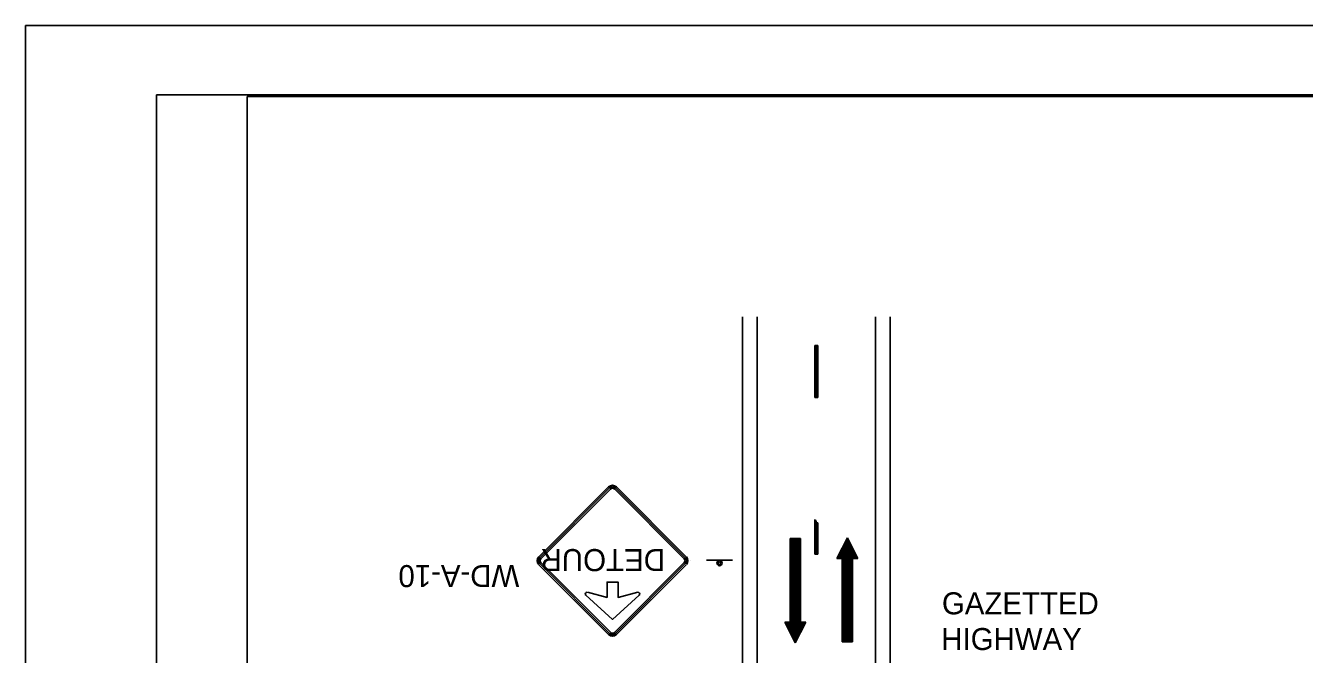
# Model space of a CAD drawing. Extents: x 1482 to 1692, y 225 to 494.
# Drawn here: x 1482.4 to 1587.1, y 442.2 to 493.6 of the extents above; entities that cross this region are included whole.
import ezdxf

# ---------------------------------------------------------------- set-up
doc = ezdxf.new("R2010")
doc.units = 0
for name, color, linetype in [('Level 1', 7, 'Continuous'), ('Level 17', 7, 'Continuous'), ('Level 2', 7, 'Continuous'), ('Level 60', 7, 'Continuous')]:
    doc.layers.add(name, color=color, linetype=linetype)

msp = doc.modelspace()

# ---------------------------------------------------------------- linework, layer by layer
at = {"layer": 'Level 1'}
msp.add_line((1493.13, 487.96), (1493.13, 487.96), dxfattribs=at)
at = {"layer": 'Level 17'}
for p, q in [((1524.41, 450.17), (1530.12, 455.89)), ((1524.49, 450.08), (1530.21, 455.8)), ((1524.58, 450), (1530.3, 455.72)), ((1530.6, 455.72), (1536.32, 450)), ((1530.69, 455.8), (1536.4, 450.08)), ((1530.77, 455.89), (1536.49, 450.17)), ((1530.12, 443.8), (1524.41, 449.52)), ((1530.21, 443.89), (1524.49, 449.61)), ((1530.3, 443.97), (1524.58, 449.69)), ((1536.32, 449.69), (1530.6, 443.97)), ((1536.4, 449.61), (1530.69, 443.89)), ((1536.49, 449.52), (1530.77, 443.8)), ((1536.81, 449.85), (1536.81, 449.85)), ((1540.28, 449.88), (1538.14, 449.88)), ((1532.51, 447.26), (1532.51, 447.26)), ((1532.51, 447.26), (1532.51, 447.26)), ((1532.51, 447.26), (1532.51, 447.26))]:
    msp.add_line(p, q, dxfattribs=at)
for points in [[(1528.39, 447.26), (1530, 446.84), (1530, 448.1), (1530.9, 448.1), (1530.9, 446.84), (1532.51, 447.26)], [(1528.39, 447.26), (1530, 446.84), (1530, 448.1), (1530.9, 448.1), (1530.9, 446.84), (1532.51, 447.26)], [(1528.39, 447.26), (1530, 446.84), (1530, 448.1), (1530.9, 448.1), (1530.9, 446.84), (1532.51, 447.26)], [(1532.63, 447.02), (1530.45, 445.04), (1528.26, 447.02)], [(1532.63, 447.02), (1530.45, 445.04), (1528.26, 447.02)], [(1532.63, 447.02), (1530.45, 445.04), (1528.26, 447.02)]]:
    msp.add_lwpolyline(points, dxfattribs=at)
for radius in [0.213, 0.107]:
    msp.add_circle((1539.21, 449.65), radius, dxfattribs=at)
for centre, radius, start, end in [((1530.45, 455.56), 0.456, 45, 135), ((1530.45, 455.56), 0.336, 45, 135), ((1530.45, 455.56), 0.216, 45, 135), ((1524.73, 449.85), 0.456, 135, 225), ((1524.73, 449.85), 0.336, 135, 225), ((1536.17, 449.85), 0.336, 315, 45), ((1536.17, 449.85), 0.456, 315, 45), ((1524.73, 449.85), 0.216, 135, 225), ((1536.17, 449.85), 0.216, 315, 45), ((1528.35, 447.13), 0.137, 75.5925, 227.6952), ((1528.35, 447.13), 0.137, 75.5925, 227.6952), ((1528.35, 447.13), 0.137, 75.5925, 227.6952), ((1532.54, 447.13), 0.137, 312.3048, 104.4075), ((1532.54, 447.13), 0.137, 312.3048, 104.4075), ((1532.54, 447.13), 0.137, 312.3048, 104.4075), ((1530.45, 444.13), 0.456, 225, 315), ((1530.45, 444.13), 0.336, 225, 315), ((1530.45, 444.13), 0.216, 225, 315)]:
    msp.add_arc(centre, radius, start, end, dxfattribs=at)
at = {"layer": 'Level 2'}
for p, q in [((1541.08, 394.37), (1541.08, 469.81)), ((1542.29, 394.37), (1542.29, 469.81)), ((1551.97, 394.26), (1551.97, 469.81)), ((1553.18, 394.37), (1553.18, 469.81)), ((1547, 467.45), (1547, 463.19)), ((1547, 467.45), (1547.26, 467.45)), ((1547.07, 467.45), (1547.07, 463.19)), ((1547.13, 467.45), (1547.13, 463.19)), ((1547.19, 467.45), (1547.19, 463.19)), ((1547.26, 467.45), (1547.26, 463.19)), ((1547, 463.19), (1547.26, 463.19)), ((1547, 453.23), (1547, 450.39)), ((1547.07, 453.18), (1547.07, 450.39)), ((1547.13, 453.1), (1547.13, 450.39)), ((1547.19, 453.01), (1547.19, 450.39)), ((1547.26, 452.95), (1547.26, 450.39)), ((1544.99, 444.83), (1544.99, 451.66)), ((1545.84, 451.66), (1544.99, 451.66)), ((1544.99, 443.98), (1544.99, 451.66)), ((1545.09, 443.76), (1545.09, 451.66)), ((1545.2, 443.55), (1545.2, 451.66)), ((1545.31, 443.34), (1545.31, 451.66)), ((1545.41, 443.12), (1545.41, 451.66)), ((1545.52, 443.34), (1545.52, 451.66)), ((1545.63, 443.55), (1545.63, 451.66)), ((1545.73, 443.76), (1545.73, 451.66)), ((1545.84, 444.83), (1545.84, 451.66)), ((1545.84, 443.98), (1545.84, 451.66)), ((1549.67, 451.73), (1548.82, 450.03)), ((1549.45, 451.31), (1549.45, 443.2)), ((1549.56, 451.52), (1549.56, 443.2)), ((1549.67, 451.73), (1549.67, 443.2)), ((1549.67, 451.73), (1550.52, 450.03)), ((1549.78, 451.52), (1549.78, 443.2)), ((1549.88, 451.31), (1549.88, 443.2)), ((1547, 450.39), (1547.26, 450.39)), ((1548.92, 450.24), (1548.92, 450.03)), ((1549.03, 450.45), (1549.03, 450.03)), ((1549.13, 450.67), (1549.13, 450.03)), ((1549.24, 450.88), (1549.24, 443.2)), ((1549.35, 451.09), (1549.35, 443.2)), ((1549.99, 451.09), (1549.99, 443.2)), ((1550.1, 450.88), (1550.1, 443.2)), ((1550.2, 450.67), (1550.2, 450.03)), ((1550.31, 450.45), (1550.31, 450.03)), ((1550.41, 450.24), (1550.41, 450.03)), ((1548.82, 450.03), (1549.24, 450.03)), ((1549.24, 450.03), (1549.24, 443.2)), ((1550.1, 450.03), (1550.1, 443.2)), ((1550.1, 450.03), (1550.52, 450.03)), ((1545.41, 443.12), (1544.56, 444.83)), ((1544.99, 444.83), (1544.56, 444.83)), ((1544.67, 444.62), (1544.67, 444.83)), ((1544.77, 444.4), (1544.77, 444.83)), ((1544.88, 444.19), (1544.88, 444.83)), ((1545.41, 443.12), (1546.27, 444.83)), ((1546.27, 444.83), (1545.84, 444.83)), ((1545.95, 444.19), (1545.95, 444.83)), ((1546.05, 444.4), (1546.05, 444.83)), ((1546.16, 444.62), (1546.16, 444.83)), ((1549.24, 443.2), (1550.1, 443.2))]:
    msp.add_line(p, q, dxfattribs=at)
at = {"layer": 'Level 60'}
for points in [[(1482.41, 493.62), (1692.41, 493.62), (1692.41, 224.63), (1482.41, 224.63)], [(1493.13, 487.96), (1687.52, 487.96), (1687.52, 230.21), (1493.13, 230.21)], [(1500.54, 487.82), (1687.41, 487.82), (1687.41, 230.44), (1500.54, 230.44)]]:
    msp.add_lwpolyline(points, close=True, dxfattribs=at)

# ---------------------------------------------------------------- texts
at = {"layer": 'Level 17'}
for s, height, rotation, p in [('DETOUR', 1.806, 180, (1534.75, 450.8)), ('WD-A-10', 1.8, 180, (1522.82, 449.49)), ('GAZETTED', 1.8, 360, (1557.41, 445.46)), ('HIGHWAY', 1.8, 360, (1557.36, 442.54))]:
    msp.add_text(s, height=height, rotation=rotation, dxfattribs=at).set_placement(p)

doc.saveas('drawing.dxf')
